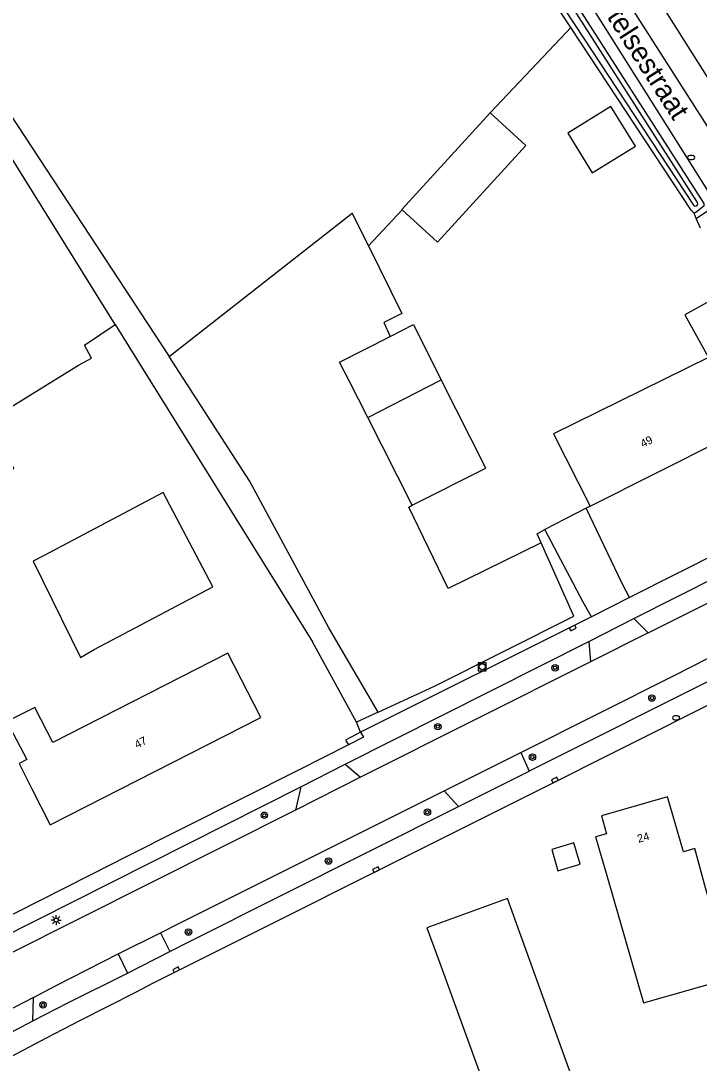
# Model space of a CAD drawing. Extents: x 140000 to 143000, y 403500 to 406000.
# Drawn here: x 140940.3 to 141024.3, y 404792.3 to 404921.3 of the extents above; entities that cross this region are included whole.
import ezdxf

# ---------------------------------------------------------------- set-up
doc = ezdxf.new("R2010")
doc.units = 0
for name, color, linetype in [('gg-afsc-erfafscheiding', 7, 'Continuous'), ('gg-afsc-hekwerk', 7, 'Continuous'), ('gg-anno-huisnummerreeks BGT', 7, 'Continuous'), ('gg-anno-openbare ruimte label', 7, 'Continuous'), ('gg-bbg-bijgebouw', 7, 'Continuous'), ('gg-bbg-hoofdgebouw', 7, 'Continuous'), ('gg-bbg-luifel en loopbrug', 7, 'Continuous'), ('gg-bbg-open loods', 7, 'Continuous'), ('gg-knt-bronhoudergrens', 7, 'Continuous'), ('gg-knt-verharding', 7, 'Continuous'), ('gg-knt-verharding nz', 7, 'Continuous'), ('gg-kntw-bovenkant insteek waterloop', 7, 'Continuous'), ('gg-kntw-waterlijn', 7, 'Continuous'), ('gt-grn-vlakafsluiter', 7, 'Continuous'), ('gt-symb-boom', 7, 'Continuous'), ('gt-symb-brandkraan', 7, 'Continuous'), ('gt-symb-kolk', 7, 'Continuous'), ('gt-symb-lichtmast', 7, 'Continuous'), ('gt-symb-rioolschacht', 7, 'Continuous')]:
    doc.layers.add(name, color=color, linetype=linetype)

# ---------------------------------------------------------------- blocks, each defined once
blk = doc.blocks.new('gt0-BOOM')
at = {"layer": 'gt-symb-boom'}
for radius in [0.4, 0.2]:
    blk.add_circle((0, 0), radius, dxfattribs=at)
blk = doc.blocks.new('gt0-KOLK')
at = {"layer": 'gt-symb-kolk'}
blk.add_lwpolyline([(0, 0), (0.38, 0), (0.38, 0.4), (-0.37, 0.4), (-0.37, 0), (0, 0)], dxfattribs=at)
blk = doc.blocks.new('gt0-BR')
at = {"layer": 'gt-symb-brandkraan'}
for centre, radius, start, end in [((-0.24, 0), 0.206, 107.5669, 252.4331), ((0.6, -2.66), 3, 106.892, 107.5669), ((0, -0.69), 0.938, 73.108, 106.892), ((-0.6, -2.66), 3, 72.4331, 73.108), ((0.24, 0), 0.206, 287.567, 72.4331), ((0.6, 2.66), 3, 252.4331, 253.108), ((0, 0.69), 0.938, 253.108, 286.8921), ((-0.6, 2.66), 3, 286.8921, 287.567)]:
    blk.add_arc(centre, radius, start, end, dxfattribs=at)
blk = doc.blocks.new('gt0-RS')
at = {"layer": 'gt-symb-rioolschacht'}
blk.add_lwpolyline([(-0.5, -0.5), (0.5, -0.5), (0.5, 0.5), (-0.5, 0.5)], close=True, dxfattribs=at)
blk.add_circle((0, 0), 0.375, dxfattribs=at)
blk = doc.blocks.new('gt0-LMAST')
at = {"layer": 'gt-symb-lichtmast'}
for p, q in [((-0.18, 0.17), (-0.45, 0.44)), ((-0.01, 0.25), (-0.01, 0.62)), ((0.17, 0.17), (0.44, 0.44)), ((-0.26, 0), (-0.63, 0)), ((-0.18, -0.18), (-0.45, -0.45)), ((-0.01, -0.25), (-0.01, -0.63)), ((0.44, -0.45), (0.17, -0.18)), ((0.24, 0), (0.62, 0))]:
    blk.add_line(p, q, dxfattribs=at)
blk.add_circle((-0.01, 0), 0.25, dxfattribs=at)

msp = doc.modelspace()

# ---------------------------------------------------------------- linework, layer by layer
at = {"layer": 'gg-afsc-erfafscheiding'}
for p, q in [((141008.04, 404941.68), (141034.56, 404899.71)), ((141023.96, 404896.88), (141023.68, 404897.52)), ((141010.81, 404861.24), (141010.3, 404860.98))]:
    msp.add_line(p, q, dxfattribs=at)
for points in [[(140998.43, 404909.93), (141007.84, 404919.9), (141008.4, 404920.51)], [(140982.38, 404833.26), (140980.53, 404832.28), (140980.88, 404831.71)]]:
    msp.add_lwpolyline(points, dxfattribs=at)
at = {"layer": 'gg-afsc-hekwerk'}
for p, q in [((140998.43, 404909.93), (141007.84, 404919.9)), ((140958.66, 404879.79), (140981.33, 404897.52)), ((140983.38, 404893.48), (140981.33, 404897.52)), ((140983.38, 404893.48), (140987.52, 404897.95))]:
    msp.add_line(p, q, dxfattribs=at)
at = {"layer": 'gg-bbg-bijgebouw'}
for p, q in [((140986.03, 404882.26), (140988.92, 404883.73)), ((140979.79, 404879.08), (140986.03, 404882.26)), ((140983.26, 404872.24), (140992.37, 404876.87))]:
    msp.add_line(p, q, dxfattribs=at)
for points in [[(141016.41, 404905.8), (141013.37, 404910.72), (141008.04, 404907.44), (141011.08, 404902.51), (141016.41, 404905.8)], [(140998.43, 404909.93), (140987.49, 404897.97), (140987.52, 404897.95)], [(140998.43, 404909.93), (141002.84, 404905.9), (140991.91, 404893.94), (140987.52, 404897.95)], [(140988.92, 404883.73), (140990.12, 404881.31), (140992.37, 404876.87)], [(140983.26, 404872.24), (140980.96, 404876.77), (140979.79, 404879.08)], [(140947.7, 404842.53), (140949.4, 404843.5), (140964.09, 404851.26), (140957.93, 404862.93), (140943.18, 404855.15), (140941.84, 404854.45), (140947.7, 404842.53)], [(141002.28, 404807.96), (141000.58, 404812.66), (140990.59, 404809.03), (140992.3, 404804.33), (141000.03, 404783.09), (141009.96, 404786.71), (141002.28, 404807.96)]]:
    msp.add_lwpolyline(points, dxfattribs=at)
at = {"layer": 'gg-bbg-hoofdgebouw'}
msp.add_line((141010.81, 404861.24), (141028.43, 404870.13), dxfattribs=at)
for points in [[(141033.85, 404872.86), (141029.01, 404881.67), (141028.92, 404881.62), (141026.04, 404886.86), (141022.55, 404884.94), (141025.45, 404879.66), (141006.29, 404870.21), (141010.81, 404861.24)], [(140940.09, 404829.4), (140941.69, 404826.26), (140943.96, 404821.8), (140970.01, 404835.1), (140965.96, 404843.03), (140944.28, 404831.97), (140942.06, 404836.32), (140938.59, 404834.6), (140941.03, 404829.9), (140940.09, 404829.4)], [(141022.36, 404818.44), (141020.4, 404825.27), (141012.22, 404822.92), (141012.85, 404820.7), (141011.47, 404820.31), (141012.88, 404815.51), (141017.4, 404799.74), (141028.31, 404802.86), (141025.09, 404814.01), (141023.77, 404818.85), (141022.36, 404818.44)]]:
    msp.add_lwpolyline(points, dxfattribs=at)
at = {"layer": 'gg-bbg-luifel en loopbrug'}
msp.add_lwpolyline([(141006.07, 404818.75), (141006.82, 404816.12), (141009.59, 404816.92), (141008.81, 404819.56), (141006.07, 404818.75)], dxfattribs=at)
at = {"layer": 'gg-bbg-open loods'}
msp.add_line((140988.78, 404861.37), (140983.26, 404872.24), dxfattribs=at)
msp.add_lwpolyline([(140988.78, 404861.37), (140997.91, 404865.95), (140992.37, 404876.87)], dxfattribs=at)
at = {"layer": 'gg-knt-bronhoudergrens'}
msp.add_line((140983.38, 404893.48), (140987.52, 404897.95), dxfattribs=at)
for points in [[(140958.66, 404879.79), (140981.33, 404897.52), (140983.38, 404893.48)], [(140889.94, 404868.9), (140891.84, 404869.02), (140912.61, 404882.07), (140927.5, 404858.33), (140939.45, 404865.96), (140935.95, 404871.61), (140947.46, 404878.69), (140949.05, 404879.55), (140948.19, 404881.2), (140951.99, 404883.73)], [(141004.73, 404856.69), (141004.24, 404857.84), (141005.19, 404858.35)], [(140984.57, 404835.73), (140991.55, 404838.98), (141008.77, 404847.64), (141004.73, 404856.69)]]:
    msp.add_lwpolyline(points, dxfattribs=at)
at = {"layer": 'gg-knt-verharding'}
for p, q in [((141004.07, 404941.58), (141036.15, 404891.25)), ((141000.7, 404939.45), (141026.47, 404898.56)), ((141023.96, 404896.88), (141026.47, 404898.56)), ((141024.49, 404895.65), (141023.96, 404896.88)), ((141010.3, 404860.98), (141005.19, 404858.35)), ((141034.03, 404859.22), (141015.68, 404849.92)), ((141047.02, 404850.39), (141003.24, 404828.43)), ((141015.68, 404849.92), (141010.98, 404847.54)), ((141010.98, 404847.54), (140982.38, 404833.26)), ((141010.63, 404844.5), (141016.24, 404847.33)), ((141016.24, 404847.33), (141018.01, 404845.58)), ((140980.48, 404829.29), (141010.63, 404844.5)), ((141010.63, 404844.5), (141010.84, 404841.98)), ((141010.84, 404841.98), (140982.38, 404827.68)), ((141002.21, 404830.77), (141003.24, 404828.43)), ((140974.97, 404826.51), (140980.48, 404829.29)), ((140980.48, 404829.29), (140982.38, 404827.68)), ((140994.5, 404824.05), (141003.24, 404828.43)), ((140974.97, 404826.51), (140974.31, 404823.62)), ((140992.72, 404826.02), (140994.5, 404824.05)), ((140957.6, 404808.44), (140958.76, 404806.11)), ((140952.37, 404805.81), (140953.5, 404803.45)), ((140953.5, 404803.45), (140958.76, 404806.11)), ((140941.81, 404797.52), (140941.86, 404800.43)), ((140937.71, 404795.37), (140941.81, 404797.52))]:
    msp.add_line(p, q, dxfattribs=at)
for points in [[(141016.24, 404847.33), (141037.35, 404857.98), (141046.52, 404862.5)], [(141015.68, 404849.92), (141014.78, 404851.68), (141010.3, 404860.98)], [(141010.98, 404847.54), (141009.93, 404849.37), (141005.19, 404858.35)], [(141018.01, 404845.58), (141033.23, 404853.16), (141039.18, 404854.6)], [(141002.21, 404830.77), (141021.29, 404840.33), (141035.69, 404847.65), (141040.79, 404851.5)], [(140912.41, 404779.39), (140912.97, 404779.71), (140913.21, 404779.18), (140930.77, 404788.76), (140938.49, 404792.8), (140943.49, 404795.42), (140947.69, 404797.61), (140954.54, 404801.09), (140956.67, 404802.18), (140959.31, 404803.5), (140996.81, 404822.29), (141003.91, 404825.85), (141026.47, 404837.15)], [(140982.38, 404833.26), (140982.74, 404832.64), (140980.88, 404831.71)], [(140980.88, 404831.71), (140974.68, 404828.58), (140953.12, 404817.71), (140951.64, 404816.96), (140936.78, 404809.47), (140931.38, 404806.66)], [(140928.71, 404803.04), (140937.54, 404807.63), (140974.97, 404826.51)], [(140957.6, 404808.44), (140960.04, 404809.67), (140992.72, 404826.02)], [(140958.76, 404806.11), (140961.21, 404807.35), (140994.5, 404824.05)], [(140974.31, 404823.62), (140938.67, 404805.71), (140931.24, 404801.83)], [(140941.86, 404800.43), (140944.59, 404801.86), (140952.37, 404805.81)], [(140941.81, 404797.52), (140946.11, 404799.77), (140953.5, 404803.45)]]:
    msp.add_lwpolyline(points, dxfattribs=at)
at = {"layer": 'gg-knt-verharding nz'}
for p, q in [((141018.01, 404845.58), (141010.84, 404841.98)), ((140992.72, 404826.02), (141002.21, 404830.77)), ((140982.38, 404827.68), (140974.31, 404823.62)), ((140952.37, 404805.81), (140957.6, 404808.44)), ((140941.86, 404800.43), (140935.06, 404796.87))]:
    msp.add_line(p, q, dxfattribs=at)
at = {"layer": 'gg-kntw-bovenkant insteek waterloop'}
for p, q in [((140951.99, 404883.73), (140956.33, 404876.75)), ((140956.33, 404876.75), (140976.44, 404844.46)), ((140984.57, 404835.73), (140978.46, 404846.17)), ((140981.89, 404834.5), (140976.44, 404844.46)), ((140984.57, 404835.73), (140981.89, 404834.5))]:
    msp.add_line(p, q, dxfattribs=at)
for points in [[(140888.51, 405040.16), (140863.97, 405024.78), (140917.53, 404942.41), (140958.66, 404879.79)], [(140951.99, 404883.73), (140933.63, 404913.2), (140891.63, 404978.71), (140861.84, 405022.76)], [(140975.14, 404977.19), (140992.67, 404949.76), (141006.99, 404926.69), (141024.87, 404898.72), (141024.9, 404898.37), (141023.96, 404897.66), (141023.68, 404897.52)], [(141008.4, 404920.51), (141005.01, 404925.65), (140990.61, 404948.64), (140973.31, 404975.94)], [(141023.68, 404897.52), (141023.32, 404897.89), (141008.4, 404920.51)], [(140978.46, 404846.17), (140968.62, 404864.37), (140958.66, 404879.79)]]:
    msp.add_lwpolyline(points, dxfattribs=at)
at = {"layer": 'gg-kntw-waterlijn'}
for points in [[(140942.04, 405025.17), (140947.55, 405017.71), (140956.48, 405004.98), (140974.97, 404976.34), (140992.16, 404949.44), (141006.48, 404926.37), (141024.08, 404898.84)], [(140941.21, 405024.59), (140946.72, 405017.13), (140955.63, 405004.43), (140974.13, 404975.77), (140991.12, 404948.96), (141005.52, 404925.98), (141008.9, 404920.85), (141023.62, 404898.52)]]:
    msp.add_lwpolyline(points, dxfattribs=at)
msp.add_arc((141023.86, 404898.67), 0.278, 213.6667, 35.6584, dxfattribs=at)
at = {"layer": 'gt-grn-vlakafsluiter'}
msp.add_line((140982.38, 404833.26), (140981.89, 404834.5), dxfattribs=at)
for points in [[(140983.38, 404893.48), (140987.51, 404885.1), (140985.26, 404883.98), (140986.03, 404882.26)], [(141004.73, 404856.69), (140993.23, 404851.04), (140988.37, 404861.12), (140988.78, 404861.37)]]:
    msp.add_lwpolyline(points, dxfattribs=at)

# ---------------------------------------------------------------- block references
at = {"layer": 'gt-symb-boom'}
for p in [(141006.47, 404841.24), (141018.46, 404837.49), (140991.95, 404833.95), (141003.66, 404830.18), (140970.46, 404822.98), (140990.66, 404823.36), (140978.41, 404817.31), (140961.07, 404808.52), (140943.05, 404799.5)]:
    msp.add_blockref('gt0-BOOM', p, dxfattribs=at)
at = {"layer": 'gt-symb-brandkraan'}
for p in [(141023.32, 404904.41), (141021.45, 404835.04)]:
    msp.add_blockref('gt0-BR', p, dxfattribs=at)
at = {"layer": 'gt-symb-kolk'}
for p, rotation in [((141008.57, 404846.33), -153.47464482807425), ((141006.53, 404827.16), 26.615573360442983), ((140984.38, 404816.06), 26.6083586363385), ((140959.63, 404803.67), 26.6083586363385)]:
    msp.add_blockref('gt0-KOLK', p, dxfattribs=dict(at, rotation=rotation))
at = {"layer": 'gt-symb-lichtmast'}
msp.add_blockref('gt0-LMAST', (140944.69, 404810), dxfattribs=at)
at = {"layer": 'gt-symb-rioolschacht'}
msp.add_blockref('gt0-RS', (140997.45, 404841.37), dxfattribs=at)

# ---------------------------------------------------------------- texts
at = {"layer": 'gg-anno-huisnummerreeks BGT'}
for s, rotation, p in [('49', 26.8, (141017.35, 404868.46)), ('47', 27, (140954.7, 404831.22)), ('24', 16, (141016.81, 404819.56))]:
    msp.add_text(s, height=1, rotation=rotation, dxfattribs=at).set_placement(p)
at = {"layer": 'gg-anno-openbare ruimte label'}
msp.add_text('Biezenmortelsestraat', height=2.5, rotation=302.7, dxfattribs=at).set_placement((141004.18, 404935.3))

doc.saveas('drawing.dxf')
